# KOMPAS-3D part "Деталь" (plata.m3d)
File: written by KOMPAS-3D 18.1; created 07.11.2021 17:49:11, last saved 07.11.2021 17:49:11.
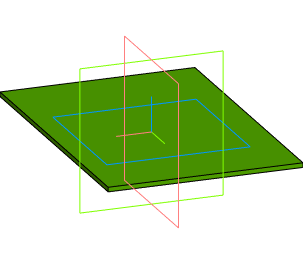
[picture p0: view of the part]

Document properties: Автор: 111; Полное имя файла: C:\Users\admin\Desktop\ffb\plata.m3d

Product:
- Part/product: Деталь
    Масса: 0.0854733

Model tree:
1. Эскиз:1
2. Элемент выдавливания:1
     Расстояние 1 = 1.6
